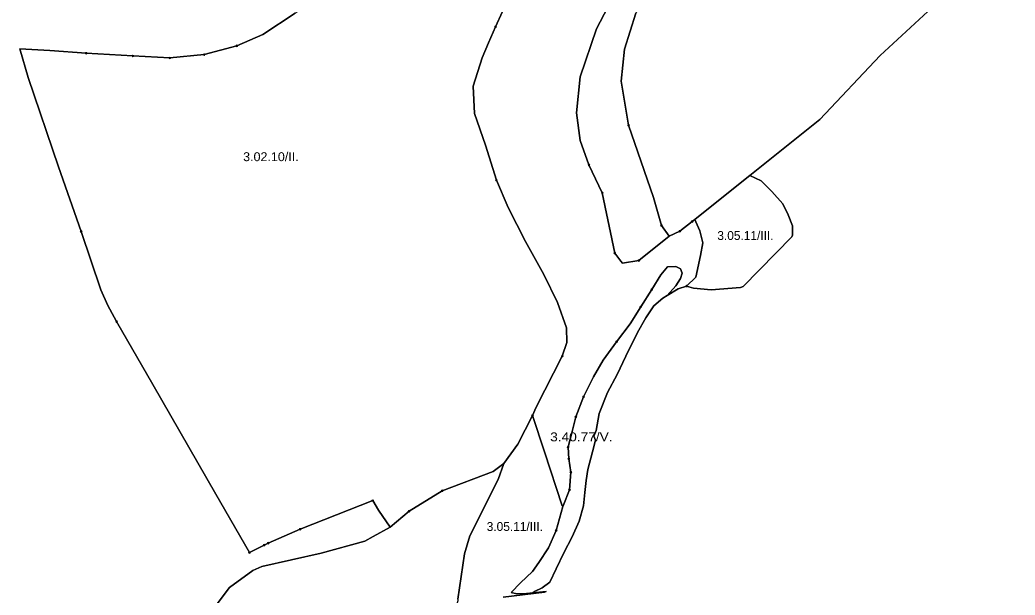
# Model space of a CAD drawing. Extents: x -650455 to -642254, y -1075222 to -1066610.
# Drawn here: x -646512 to -645394, y -1068906 to -1068260 of the extents above; entities that cross this region are included whole.
import ezdxf
from ezdxf.enums import TextEntityAlignment as Align

# ---------------------------------------------------------------- set-up
doc = ezdxf.new("R2010")
doc.units = 0
doc.header["$LTSCALE"] = 4
doc.header["$PDMODE"] = 32
doc.header["$PDSIZE"] = 2
for name, color, linetype, lineweight in [('1', 7, 'Continuous', 25), ('11', 7, 'Continuous', 13), ('12', 7, 'Continuous', 13), ('13', 7, 'Continuous', 13), ('14', 7, 'Continuous', 13), ('15', 7, 'Continuous', 13)]:
    doc.layers.add(name, color=color, linetype=linetype, lineweight=lineweight)
doc.layers.add('2', color=7, linetype='Continuous')

msp = doc.modelspace()

# ---------------------------------------------------------------- linework, layer by layer
at = {"layer": '1'}
for points in [[(-645835.5, -1068533.001), (-645837.25, -1068530.626), (-645844, -1068521.5), (-645858, -1068454), (-645873, -1068422.501), (-645883, -1068395.001), (-645887, -1068364), (-645883, -1068323.5), (-645864.5, -1068269.501), (-645830.5, -1068204.001)], [(-645830.5, -1068204.001), (-645864.5, -1068269.501), (-645883, -1068323.5), (-645887, -1068364), (-645883, -1068395.001), (-645873, -1068422.501), (-645858, -1068454), (-645844, -1068521.5), (-645837.25, -1068530.626), (-645835.5, -1068533.001), (-645817, -1068530), (-645783, -1068502.5), (-645771, -1068497), (-645757, -1068486), (-645754.063, -1068483.625), (-645754.054, -1068483.65), (-645753.062, -1068486.376), (-645748.375, -1068496.625), (-645745.188, -1068510), (-645747.562, -1068524.125), (-645753.062, -1068548.501), (-645763.25, -1068558.626)], [(-645962.438, -1068232.625), (-645977.937, -1068267.25), (-645985.875, -1068285.501), (-645985.9, -1068285.558), (-645993.125, -1068302.125), (-646002.938, -1068334.001), (-646001.687, -1068364.75), (-645989.375, -1068400.25), (-645977.063, -1068439.625), (-645963.688, -1068470.25), (-645944.375, -1068508.625), (-645923.687, -1068545.75), (-645908.5, -1068577.001), (-645898.188, -1068605.625), (-645897.875, -1068622.125), (-645903, -1068637.501), (-645932.5, -1068694.501), (-645936.5, -1068704), (-645953, -1068736), (-645968.5, -1068758.001), (-645980.5, -1068767.001), (-646038, -1068788.5), (-646075, -1068811.501), (-646096.5, -1068829.5), (-646109.312, -1068810.126), (-646116, -1068799.625), (-646197.562, -1068831.751), (-646233.312, -1068847.375), (-646237.938, -1068849.5), (-646254.375, -1068858), (-646292.063, -1068792.5), (-646362.938, -1068669.125), (-646403.688, -1068598.376), (-646411.5, -1068584.501)], [(-645989.375, -1068400.25), (-646001.687, -1068364.75), (-646002.938, -1068334.001), (-645993.125, -1068302.125), (-645985.9, -1068285.558), (-645985.875, -1068285.501), (-645977.937, -1068267.25), (-645962.438, -1068232.625)], [(-645841.188, -1068657.875), (-645831.75, -1068637.375), (-645818.375, -1068610.626), (-645808.938, -1068594.126), (-645800.25, -1068580.751), (-645790.063, -1068572.125), (-645785.188, -1068569.251), (-645772.75, -1068561.876), (-645763.25, -1068558.626), (-645755.437, -1068561.125), (-645735.75, -1068562.626), (-645702.75, -1068560.251), (-645699.65, -1068559.035), (-645699.562, -1068559), (-645645.187, -1068503.251), (-645645.161, -1068503.178), (-645644.5, -1068501.376), (-645644.5, -1068490.751), (-645649.125, -1068478.5), (-645655.188, -1068466.25), (-645667.438, -1068452.5), (-645679.625, -1068440.376), (-645692.438, -1068434.501), (-645613.5, -1068371.5), (-645546, -1068299.5), (-645487.5, -1068245.501)], [(-645487.5, -1068245.501), (-645546, -1068299.5), (-645613.5, -1068371.5), (-645692.438, -1068434.501), (-645712.513, -1068450.504), (-645712.527, -1068450.515), (-645754.063, -1068483.625), (-645757, -1068486), (-645771, -1068497), (-645783, -1068502.5), (-645791.5, -1068490.5), (-645800.5, -1068459.001), (-645828.5, -1068378.001), (-645837, -1068328.5), (-645833, -1068292.501), (-645820.5, -1068252.001)], [(-646203.125, -1068252.001), (-646239.25, -1068276.126), (-646268.75, -1068288.751), (-646305.5, -1068298.626), (-646344.062, -1068302.375), (-646385.313, -1068300.126), (-646438, -1068297.125), (-646478.625, -1068294.125), (-646512.375, -1068292.25), (-646503, -1068324.25), (-646468.875, -1068424.5), (-646443.563, -1068497.376), (-646421.312, -1068562.75), (-646413.5, -1068580.251), (-646411.5, -1068584.501), (-646403.688, -1068598.376), (-646362.938, -1068669.125), (-646292.063, -1068792.5), (-646254.375, -1068858), (-646237.938, -1068849.5), (-646233.312, -1068847.375), (-646197.562, -1068831.751), (-646116, -1068799.625), (-646109.312, -1068810.126), (-646096.5, -1068829.5), (-646115.5, -1068840.001), (-646125, -1068845), (-646174, -1068858.5), (-646240.5, -1068873.5), (-646250.5, -1068878), (-646277, -1068897.001), (-646294, -1068920.001)], [(-646411.5, -1068584.501), (-646413.5, -1068580.251), (-646421.312, -1068562.75), (-646443.563, -1068497.376), (-646468.875, -1068424.5), (-646503, -1068324.25), (-646512.375, -1068292.25), (-646478.625, -1068294.125), (-646438, -1068297.125), (-646385.313, -1068300.126), (-646344.062, -1068302.375), (-646305.5, -1068298.626), (-646268.75, -1068288.751), (-646239.25, -1068276.126), (-646203.125, -1068252.001)], [(-645820.5, -1068252.001), (-645833, -1068292.501), (-645837, -1068328.5), (-645828.5, -1068378.001), (-645800.5, -1068459.001), (-645791.5, -1068490.5), (-645783, -1068502.5), (-645817, -1068530), (-645835.5, -1068533.001)], [(-645763.25, -1068558.626), (-645772.75, -1068561.876), (-645785.188, -1068569.251), (-645775.313, -1068558.5), (-645770.25, -1068550.25), (-645768.438, -1068544.251), (-645770.25, -1068539.25), (-645774.534, -1068537.109), (-645775.75, -1068536.501), (-645784.938, -1068536.875), (-645792.312, -1068546.126), (-645802.5, -1068562.5), (-645814.875, -1068581.751), (-645826.813, -1068601.001), (-645841.938, -1068621.125), (-645857.062, -1068641.751), (-645868.063, -1068660.5), (-645879.063, -1068683), (-645887.75, -1068705.501), (-645893.562, -1068729.5), (-645894.062, -1068730.001), (-645896.437, -1068739.375), (-645895.687, -1068752.75), (-645893.312, -1068767.751), (-645894.875, -1068787.375), (-645901.938, -1068805.5), (-645902.188, -1068806.126), (-645903, -1068805.5), (-645923.062, -1068744.626), (-645936.5, -1068704), (-645932.5, -1068694.501), (-645903, -1068637.501), (-645897.875, -1068622.125), (-645898.188, -1068605.625), (-645908.5, -1068577.001), (-645923.687, -1068545.75), (-645944.375, -1068508.625), (-645963.688, -1068470.25), (-645977.063, -1068439.625), (-645989.375, -1068400.25)], [(-645896.437, -1068739.375), (-645894.062, -1068730.001), (-645893.562, -1068729.5), (-645887.75, -1068705.501), (-645879.063, -1068683), (-645868.063, -1068660.5), (-645857.062, -1068641.751), (-645841.938, -1068621.125), (-645826.813, -1068601.001), (-645814.875, -1068581.751), (-645802.5, -1068562.5), (-645792.312, -1068546.126), (-645784.938, -1068536.875), (-645775.75, -1068536.501), (-645774.534, -1068537.109), (-645770.25, -1068539.25), (-645768.438, -1068544.251), (-645770.25, -1068550.25), (-645775.313, -1068558.5), (-645785.188, -1068569.251)], [(-645785.188, -1068569.251), (-645790.063, -1068572.125), (-645800.25, -1068580.751), (-645808.938, -1068594.126), (-645818.375, -1068610.626), (-645831.75, -1068637.375), (-645841.188, -1068657.875), (-645852.187, -1068678.251), (-645861.625, -1068701.875), (-645864.75, -1068720.75), (-645867.563, -1068727.125), (-645865.75, -1068731.501), (-645868.938, -1068744.876), (-645874.438, -1068764.626), (-645876, -1068777.126), (-645877.562, -1068790.501), (-645879.125, -1068805.5), (-645883.875, -1068822.751), (-645891.75, -1068840.125), (-645901.187, -1068858.126), (-645909.812, -1068876.251), (-645916.875, -1068891.25), (-645925.563, -1068897.501), (-645934.188, -1068901.501), (-645936.187, -1068903.25), (-645943.25, -1068904.001), (-645954.125, -1068904.375), (-645960.5, -1068902.626), (-645949.938, -1068892.001), (-645936.563, -1068879.376), (-645929.5, -1068869.25), (-645918.5, -1068852.625), (-645909.812, -1068833), (-645902.196, -1068806.154), (-645902.188, -1068806.126), (-645901.938, -1068805.5), (-645894.875, -1068787.375), (-645893.312, -1068767.751), (-645895.687, -1068752.75), (-645896.437, -1068739.375)], [(-645969.5, -1068908.001), (-645923, -1068902.5), (-645921.073, -1068901.633), (-645936.187, -1068903.25), (-645934.188, -1068901.501), (-645925.563, -1068897.501), (-645916.875, -1068891.25), (-645909.812, -1068876.251), (-645901.187, -1068858.126), (-645891.75, -1068840.125), (-645883.875, -1068822.751), (-645879.125, -1068805.5), (-645877.562, -1068790.501), (-645876, -1068777.126), (-645874.438, -1068764.626), (-645868.938, -1068744.876), (-645865.75, -1068731.501), (-645867.563, -1068727.125), (-645864.75, -1068720.75), (-645861.625, -1068701.875), (-645852.187, -1068678.251), (-645841.188, -1068657.875)], [(-646020.25, -1068910.376), (-646013, -1068859.501), (-646007, -1068839.001), (-645975, -1068776.001), (-645968.5, -1068758.001), (-645953, -1068736), (-645936.5, -1068704), (-645923.062, -1068744.626), (-645903, -1068805.5), (-645902.188, -1068806.126), (-645902.196, -1068806.154), (-645909.812, -1068833), (-645918.5, -1068852.625), (-645929.5, -1068869.25), (-645936.563, -1068879.376), (-645949.938, -1068892.001), (-645960.5, -1068902.626), (-645954.125, -1068904.375), (-645943.25, -1068904.001), (-645936.187, -1068903.25), (-645921.073, -1068901.633), (-645923, -1068902.5), (-645969.5, -1068908.001)], [(-646377, -1069080), (-646359, -1069068.5), (-646343.5, -1069054.001), (-646324.5, -1069023.5), (-646306, -1068951.5), (-646294, -1068920.001), (-646277, -1068897.001), (-646250.5, -1068878), (-646240.5, -1068873.5), (-646174, -1068858.5), (-646125, -1068845), (-646115.5, -1068840.001), (-646096.5, -1068829.5), (-646075, -1068811.501), (-646038, -1068788.5), (-645980.5, -1068767.001), (-645968.5, -1068758.001), (-645975, -1068776.001), (-646007, -1068839.001), (-646013, -1068859.501), (-646020.25, -1068910.376), (-646020.269, -1068910.381), (-646020.5, -1068912.001), (-646026.5, -1068930.5)]]:
    msp.add_lwpolyline(points, dxfattribs=at)
msp.add_lwpolyline([(-645763.25, -1068558.626), (-645753.062, -1068548.501), (-645747.562, -1068524.125), (-645745.188, -1068510), (-645748.375, -1068496.625), (-645753.062, -1068486.376), (-645754.054, -1068483.65), (-645754.063, -1068483.625), (-645712.527, -1068450.515), (-645712.513, -1068450.504), (-645692.438, -1068434.501), (-645679.625, -1068440.376), (-645667.438, -1068452.5), (-645655.188, -1068466.25), (-645649.125, -1068478.5), (-645644.5, -1068490.751), (-645644.5, -1068501.376), (-645645.161, -1068503.178), (-645645.187, -1068503.251), (-645699.562, -1068559), (-645699.65, -1068559.035), (-645702.75, -1068560.251), (-645735.75, -1068562.626), (-645755.437, -1068561.125)], close=True, dxfattribs=at)
at = {"layer": '11'}
for p, q in [((-646305.5, -1068298.626), (-646268.75, -1068288.751)), ((-646344.062, -1068302.375), (-646305.5, -1068298.626))]:
    msp.add_line(p, q, dxfattribs=at)
for points in [[(-646268.75, -1068288.751), (-646239.25, -1068276.126), (-646203.125, -1068252.001), (-646167, -1068229.375), (-646136.312, -1068209.001), (-646105.312, -1068170.75), (-646076.688, -1068131.501), (-646052.625, -1068095.375)], [(-645791.5, -1068490.5), (-645783, -1068502.5), (-645771, -1068497), (-645757, -1068486), (-645754.063, -1068483.625), (-645712.527, -1068450.515), (-645712.513, -1068450.504), (-645692.438, -1068434.501), (-645613.5, -1068371.5), (-645546, -1068299.5), (-645487.5, -1068245.501), (-645456, -1068226.5), (-645434.909, -1068222.163), (-645420.75, -1068219.25), (-645398.687, -1068220.501), (-645421.625, -1068203.625)], [(-645369.687, -1068238.75), (-645398.687, -1068220.501), (-645420.75, -1068219.25), (-645434.909, -1068222.163), (-645456, -1068226.5), (-645487.5, -1068245.501), (-645546, -1068299.5), (-645613.5, -1068371.5), (-645692.438, -1068434.501), (-645679.625, -1068440.376), (-645667.438, -1068452.5), (-645655.188, -1068466.25), (-645649.125, -1068478.5), (-645644.5, -1068490.751), (-645644.5, -1068501.376), (-645645.161, -1068503.178), (-645645.187, -1068503.251), (-645699.562, -1068559), (-645699.65, -1068559.035), (-645702.75, -1068560.251), (-645735.75, -1068562.626), (-645755.437, -1068561.125), (-645763.25, -1068558.626)], [(-645806.5, -1068229.501), (-645820.5, -1068252.001), (-645833, -1068292.501), (-645837, -1068328.5), (-645828.5, -1068378.001)], [(-646443.563, -1068497.376), (-646468.875, -1068424.5), (-646503, -1068324.25), (-646512.375, -1068292.25), (-646478.625, -1068294.125), (-646438, -1068297.125)], [(-646438, -1068297.125), (-646385.313, -1068300.126), (-646344.062, -1068302.375)], [(-645828.5, -1068378.001), (-645800.5, -1068459.001), (-645791.5, -1068490.5)], [(-646403.688, -1068598.376), (-646411.5, -1068584.501), (-646413.5, -1068580.251), (-646421.312, -1068562.75), (-646443.563, -1068497.376)], [(-645763.25, -1068558.626), (-645772.75, -1068561.876), (-645785.188, -1068569.251), (-645790.063, -1068572.125), (-645800.25, -1068580.751), (-645808.938, -1068594.126), (-645818.375, -1068610.626), (-645831.75, -1068637.375), (-645841.188, -1068657.875), (-645852.187, -1068678.251), (-645861.625, -1068701.875), (-645864.75, -1068720.75), (-645867.563, -1068727.125), (-645865.75, -1068731.501), (-645868.938, -1068744.876), (-645874.438, -1068764.626), (-645876, -1068777.126), (-645877.562, -1068790.501), (-645879.125, -1068805.5), (-645883.875, -1068822.751), (-645891.75, -1068840.125), (-645901.187, -1068858.126), (-645909.812, -1068876.251), (-645916.875, -1068891.25), (-645925.563, -1068897.501), (-645934.188, -1068901.501), (-645936.187, -1068903.25), (-645921.073, -1068901.633), (-645923, -1068902.5), (-645969.5, -1068908.001)], [(-646233.312, -1068847.375), (-646237.938, -1068849.5), (-646254.375, -1068858), (-646292.063, -1068792.5), (-646362.938, -1068669.125), (-646403.688, -1068598.376)], [(-646377, -1069080), (-646359, -1069068.5), (-646343.5, -1069054.001), (-646324.5, -1069023.5), (-646306, -1068951.5), (-646294, -1068920.001), (-646277, -1068897.001), (-646250.5, -1068878), (-646240.5, -1068873.5), (-646174, -1068858.5), (-646125, -1068845), (-646115.5, -1068840.001), (-646096.5, -1068829.5), (-646109.312, -1068810.126), (-646116, -1068799.625)], [(-646116, -1068799.625), (-646197.562, -1068831.751), (-646233.312, -1068847.375)]]:
    msp.add_lwpolyline(points, dxfattribs=at)
for p in [(-646268.75, -1068288.751), (-646438, -1068297.125), (-646344.062, -1068302.375), (-646305.5, -1068298.626), (-645828.5, -1068378.001), (-646443.563, -1068497.376), (-645763.25, -1068558.626), (-646403.688, -1068598.376), (-646116, -1068799.625), (-646233.312, -1068847.375)]:
    msp.add_point(p, dxfattribs=at)
at = {"layer": '12'}
for p, q in [((-645977.937, -1068267.25), (-645962.438, -1068232.625)), ((-646344.062, -1068302.375), (-646385.313, -1068300.126)), ((-646305.5, -1068298.626), (-646344.062, -1068302.375)), ((-646254.375, -1068858), (-646237.938, -1068849.5))]:
    msp.add_line(p, q, dxfattribs=at)
for points in [[(-646203.125, -1068252.001), (-646239.25, -1068276.126), (-646268.75, -1068288.751), (-646305.5, -1068298.626)], [(-645903, -1068637.501), (-645897.875, -1068622.125), (-645898.188, -1068605.625), (-645908.5, -1068577.001), (-645923.687, -1068545.75), (-645944.375, -1068508.625), (-645963.688, -1068470.25), (-645977.063, -1068439.625), (-645989.375, -1068400.25), (-646001.687, -1068364.75), (-646002.938, -1068334.001), (-645993.125, -1068302.125), (-645985.9, -1068285.558), (-645985.875, -1068285.501), (-645977.937, -1068267.25)], [(-646385.313, -1068300.126), (-646438, -1068297.125), (-646478.625, -1068294.125), (-646512.375, -1068292.25), (-646503, -1068324.25), (-646468.875, -1068424.5), (-646443.563, -1068497.376), (-646421.312, -1068562.75), (-646413.5, -1068580.251), (-646411.5, -1068584.501), (-646403.688, -1068598.376), (-646362.938, -1068669.125), (-646292.063, -1068792.5), (-646254.375, -1068858)], [(-645936.5, -1068704), (-645932.5, -1068694.501), (-645903, -1068637.501)], [(-646075, -1068811.501), (-646038, -1068788.5), (-645980.5, -1068767.001), (-645968.5, -1068758.001), (-645953, -1068736), (-645936.5, -1068704)], [(-646197.562, -1068831.751), (-646116, -1068799.625), (-646109.312, -1068810.126), (-646096.5, -1068829.5), (-646075, -1068811.501)], [(-646237.938, -1068849.5), (-646233.312, -1068847.375), (-646197.562, -1068831.751)]]:
    msp.add_lwpolyline(points, dxfattribs=at)
for p in [(-645977.937, -1068267.25), (-646385.313, -1068300.126), (-646344.062, -1068302.375), (-646305.5, -1068298.626), (-645903, -1068637.501), (-645936.5, -1068704), (-646075, -1068811.501), (-646197.562, -1068831.751), (-646237.938, -1068849.5), (-646254.375, -1068858)]:
    msp.add_point(p, dxfattribs=at)
at = {"layer": '13'}
for points in [[(-645677, -1067974.001), (-645677, -1067999), (-645677.381, -1068000), (-645681, -1068009.501), (-645697.5, -1068040.5), (-645731.5, -1068085.5), (-645830.5, -1068204.001), (-645864.5, -1068269.501), (-645883, -1068323.5), (-645887, -1068364), (-645883, -1068395.001), (-645873, -1068422.501), (-645858, -1068454), (-645844, -1068521.5)], [(-645791.5, -1068490.5), (-645800.5, -1068459.001), (-645828.5, -1068378.001), (-645837, -1068328.5), (-645833, -1068292.501), (-645820.5, -1068252.001), (-645806.5, -1068229.501), (-645769.5, -1068189.001)], [(-645844, -1068521.5), (-645837.25, -1068530.626), (-645835.5, -1068533.001), (-645817, -1068530), (-645783, -1068502.5), (-645791.5, -1068490.5)], [(-645969.5, -1068908.001), (-645923, -1068902.5), (-645921.073, -1068901.633), (-645936.187, -1068903.25), (-645943.25, -1068904.001), (-645954.125, -1068904.375), (-645960.5, -1068902.626), (-645949.938, -1068892.001), (-645936.563, -1068879.376), (-645929.5, -1068869.25), (-645918.5, -1068852.625), (-645909.812, -1068833), (-645902.196, -1068806.154), (-645902.188, -1068806.126), (-645903, -1068805.5), (-645923.062, -1068744.626), (-645936.5, -1068704), (-645953, -1068736), (-645968.5, -1068758.001), (-645975, -1068776.001), (-646007, -1068839.001), (-646013, -1068859.501), (-646020.25, -1068910.376)], [(-646241.5, -1069496.001), (-646193.5, -1069374.501), (-646167.5, -1069296), (-646158, -1069244.001), (-646160.5, -1069203.501), (-646183.5, -1069131.501), (-646202, -1069077.5), (-646206, -1069050.501), (-646201.5, -1069028), (-646192, -1069010.001), (-646156, -1068987.5), (-646026.5, -1068930.5), (-646020.5, -1068912.001), (-646020.269, -1068910.381), (-646020.25, -1068910.376), (-646013, -1068859.501), (-646007, -1068839.001), (-645975, -1068776.001), (-645968.5, -1068758.001), (-645980.5, -1068767.001), (-646038, -1068788.5)], [(-646038, -1068788.5), (-646075, -1068811.501), (-646096.5, -1068829.5), (-646115.5, -1068840.001), (-646125, -1068845), (-646174, -1068858.5), (-646240.5, -1068873.5), (-646250.5, -1068878), (-646277, -1068897.001), (-646294, -1068920.001)]]:
    msp.add_lwpolyline(points, dxfattribs=at)
msp.add_lwpolyline([(-645755.437, -1068561.125), (-645735.75, -1068562.626), (-645702.75, -1068560.251), (-645699.65, -1068559.035), (-645699.562, -1068559), (-645645.187, -1068503.251), (-645645.161, -1068503.178), (-645644.5, -1068501.376), (-645644.5, -1068490.751), (-645649.125, -1068478.5), (-645655.188, -1068466.25), (-645667.438, -1068452.5), (-645679.625, -1068440.376), (-645692.438, -1068434.501), (-645712.513, -1068450.504), (-645712.527, -1068450.515), (-645754.063, -1068483.625), (-645754.054, -1068483.65), (-645753.062, -1068486.376), (-645748.375, -1068496.625), (-645745.188, -1068510), (-645747.562, -1068524.125), (-645753.062, -1068548.501), (-645763.25, -1068558.626)], close=True, dxfattribs=at)
for p in [(-645791.5, -1068490.5), (-645844, -1068521.5), (-646038, -1068788.5)]:
    msp.add_point(p, dxfattribs=at)
at = {"layer": '14'}
for p, q in [((-645858, -1068454), (-645873, -1068422.501)), ((-645757, -1068486), (-645771, -1068497)), ((-645814.875, -1068581.751), (-645802.5, -1068562.5)), ((-645893.312, -1068767.751), (-645895.687, -1068752.75))]:
    msp.add_line(p, q, dxfattribs=at)
for points in [[(-645873, -1068422.501), (-645883, -1068395.001), (-645887, -1068364), (-645883, -1068323.5), (-645864.5, -1068269.501), (-645830.5, -1068204.001), (-645731.5, -1068085.5), (-645697.5, -1068040.5), (-645681, -1068009.501), (-645677.381, -1068000), (-645677, -1067999), (-645677, -1067974.001), (-645668, -1067933.501), (-645656, -1067915.5), (-645608, -1067885.5), (-645593, -1067870.5), (-645588.5, -1067857.001), (-645590.5, -1067834.5), (-645603, -1067803.001), (-645609.5, -1067776.001), (-645608.5, -1067747.501)], [(-645735.605, -1068000), (-645729.568, -1068015.238), (-645729.57, -1068015.25), (-645798.69, -1068122.171), (-645829.66, -1068168.341), (-645867.779, -1068230.191), (-645872.671, -1068238), (-645874.15, -1068234.441), (-645882.74, -1068213.72), (-645888.25, -1068200.251), (-645917.313, -1068130.126), (-645918.062, -1068130.501), (-645936.625, -1068169.376), (-645947.25, -1068193.626), (-645962.438, -1068232.625), (-645977.937, -1068267.25), (-645985.875, -1068285.501), (-645985.9, -1068285.558), (-645993.125, -1068302.125), (-646002.938, -1068334.001), (-646001.687, -1068364.75), (-645989.375, -1068400.25), (-645977.063, -1068439.625)], [(-645977.063, -1068439.625), (-645963.688, -1068470.25), (-645944.375, -1068508.625), (-645923.687, -1068545.75), (-645908.5, -1068577.001), (-645898.188, -1068605.625), (-645897.875, -1068622.125), (-645903, -1068637.501), (-645932.5, -1068694.501), (-645936.5, -1068704), (-645923.062, -1068744.626), (-645903, -1068805.5), (-645902.188, -1068806.126), (-645901.938, -1068805.5), (-645894.875, -1068787.375), (-645893.312, -1068767.751)], [(-645817, -1068530), (-645835.5, -1068533.001), (-645837.25, -1068530.626), (-645844, -1068521.5), (-645858, -1068454)], [(-645763.25, -1068558.626), (-645753.062, -1068548.501), (-645747.562, -1068524.125), (-645745.188, -1068510), (-645748.375, -1068496.625), (-645753.062, -1068486.376), (-645754.054, -1068483.65), (-645754.063, -1068483.625), (-645757, -1068486)], [(-645771, -1068497), (-645783, -1068502.5), (-645817, -1068530)], [(-645802.5, -1068562.5), (-645792.312, -1068546.126), (-645784.938, -1068536.875), (-645775.75, -1068536.501), (-645774.534, -1068537.109), (-645770.25, -1068539.25), (-645768.438, -1068544.251), (-645770.25, -1068550.25), (-645775.313, -1068558.5), (-645785.188, -1068569.251), (-645772.75, -1068561.876), (-645763.25, -1068558.626)], [(-645841.938, -1068621.125), (-645826.813, -1068601.001), (-645814.875, -1068581.751)], [(-645887.75, -1068705.501), (-645879.063, -1068683), (-645868.063, -1068660.5), (-645857.062, -1068641.751), (-645841.938, -1068621.125)], [(-645895.687, -1068752.75), (-645896.437, -1068739.375), (-645894.062, -1068730.001), (-645893.562, -1068729.5), (-645887.75, -1068705.501)]]:
    msp.add_lwpolyline(points, dxfattribs=at)
for p in [(-645873, -1068422.501), (-645977.063, -1068439.625), (-645858, -1068454), (-645757, -1068486), (-645771, -1068497), (-645817, -1068530), (-645763.25, -1068558.626), (-645802.5, -1068562.5), (-645814.875, -1068581.751), (-645841.938, -1068621.125), (-645887.75, -1068705.501), (-645895.687, -1068752.75), (-645893.312, -1068767.751)]:
    msp.add_point(p, dxfattribs=at)
at = {"layer": '15'}
for points in [[(-645909.812, -1068833), (-645918.5, -1068852.625), (-645929.5, -1068869.25), (-645936.563, -1068879.376), (-645949.938, -1068892.001), (-645960.5, -1068902.626), (-645954.125, -1068904.375), (-645943.25, -1068904.001), (-645936.187, -1068903.25), (-645934.188, -1068901.501), (-645925.563, -1068897.501), (-645916.875, -1068891.25), (-645909.812, -1068876.251), (-645901.187, -1068858.126), (-645891.75, -1068840.125), (-645883.875, -1068822.751), (-645879.125, -1068805.5), (-645877.562, -1068790.501), (-645876, -1068777.126), (-645874.438, -1068764.626), (-645868.938, -1068744.876), (-645865.75, -1068731.501), (-645867.563, -1068727.125), (-645864.75, -1068720.75), (-645861.625, -1068701.875), (-645852.187, -1068678.251), (-645841.188, -1068657.875), (-645831.75, -1068637.375), (-645818.375, -1068610.626), (-645808.938, -1068594.126), (-645800.25, -1068580.751), (-645790.063, -1068572.125), (-645785.188, -1068569.251), (-645775.313, -1068558.5), (-645770.25, -1068550.25), (-645768.438, -1068544.251), (-645770.25, -1068539.25), (-645774.534, -1068537.109), (-645775.75, -1068536.501), (-645784.938, -1068536.875)], [(-645784.938, -1068536.875), (-645792.312, -1068546.126), (-645802.5, -1068562.5), (-645814.875, -1068581.751), (-645826.813, -1068601.001), (-645841.938, -1068621.125), (-645857.062, -1068641.751), (-645868.063, -1068660.5), (-645879.063, -1068683)], [(-645879.063, -1068683), (-645887.75, -1068705.501), (-645893.562, -1068729.5), (-645894.062, -1068730.001), (-645896.437, -1068739.375)], [(-645896.437, -1068739.375), (-645895.687, -1068752.75), (-645893.312, -1068767.751), (-645894.875, -1068787.375)], [(-645894.875, -1068787.375), (-645901.938, -1068805.5), (-645902.188, -1068806.126), (-645902.196, -1068806.154), (-645909.812, -1068833)]]:
    msp.add_lwpolyline(points, dxfattribs=at)
for p in [(-645879.063, -1068683), (-645896.437, -1068739.375), (-645894.875, -1068787.375), (-645909.812, -1068833)]:
    msp.add_point(p, dxfattribs=at)

# ---------------------------------------------------------------- texts
at = {"layer": '2'}
for s, width, p in [('3.02.10/II.', 1.05, (-646230.351, -1068418.276)), ('3.40.77/V.', 1.15, (-645881.532, -1068732.993))]:
    msp.add_text(s, height=10, dxfattribs=dict(at, width=width)).set_placement(p, align=Align.CENTER)
for p in [(-645697.182, -1068506.812), (-645956.284, -1068833.655)]:
    msp.add_text('3.05.11/III.', height=10, dxfattribs=at).set_placement(p, align=Align.CENTER)

doc.saveas('drawing.dxf')
